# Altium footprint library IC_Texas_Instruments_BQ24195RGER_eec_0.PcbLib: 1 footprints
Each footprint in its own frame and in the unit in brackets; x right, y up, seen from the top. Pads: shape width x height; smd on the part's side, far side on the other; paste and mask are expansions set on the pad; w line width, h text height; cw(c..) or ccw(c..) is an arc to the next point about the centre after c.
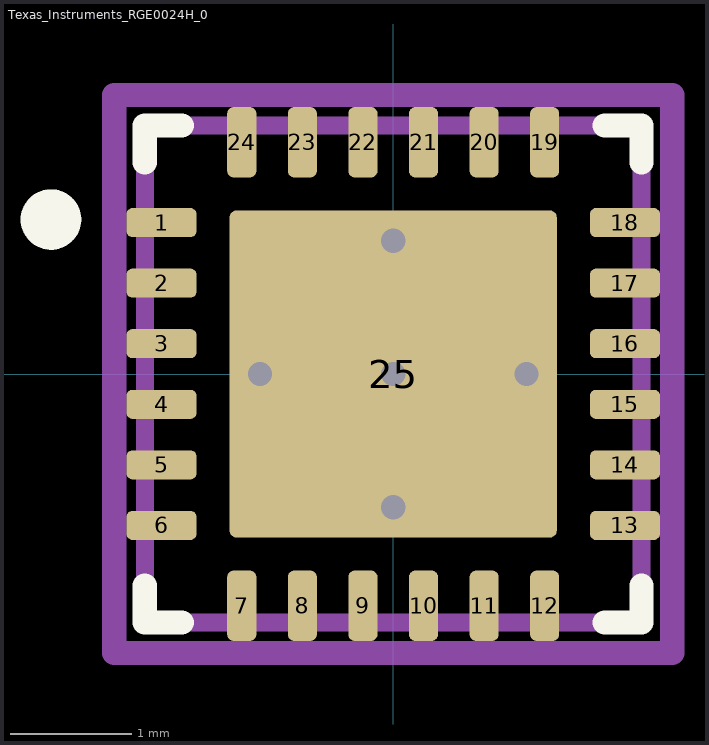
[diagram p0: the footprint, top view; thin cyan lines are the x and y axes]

## Texas_Instruments_RGE0024H_0 [mm]
pads (25):
  rrect42% 0.58x0.24 smd paste+0 mask+0: 1(-1.913,1.25) 2(-1.913,0.75) 3(-1.913,0.25) 4(-1.913,-0.25) 5(-1.913,-0.75) 6(-1.913,-1.25) 13(1.913,-1.25) 14(1.913,-0.75) 15(1.913,-0.25) 16(1.913,0.25) 17(1.913,0.75) 18(1.913,1.25)
  rrect42% 0.24x0.58 smd paste+0 mask+0: 7(-1.25,-1.913) 8(-0.75,-1.913) 9(-0.25,-1.913) 10(0.25,-1.913) 11(0.75,-1.913) 12(1.25,-1.913) 19(1.25,1.913) 20(0.75,1.913) 21(0.25,1.913) 22(-0.25,1.913) 23(-0.75,1.913) 24(-1.25,1.913)
  rrect4% 2.7x2.7 smd paste-1000 mask+0: 25(0,0)
via -1.1,0 diameter 0.5 hole 0.2
via 0,0 diameter 0.5 hole 0.2
via 1.1,0 diameter 0.5 hole 0.2
via 0,1.1 diameter 0.5 hole 0.2
via 0,-1.1 diameter 0.5 hole 0.2
Top Overlay:
  circle w0.25: c-2.825,1.275 r0.125
  lines w0.2: -2.05,-1.745 -2.05,-2.05 -1.745,-2.05 ; -2.05,1.745 -2.05,2.05 -1.745,2.05 ; 1.745,-2.05 2.05,-2.05 2.05,-1.745 ; 1.745,2.05 2.05,2.05 2.05,1.745
Top Paste:
  region: -0.1,0.15 -0.1,0.14 -0.108,0.122 -0.122,0.108 -0.14,0.1 -0.15,0.1 -1.238,0.1 -1.248,0.1 -1.266,0.108 -1.28,0.122 -1.288,0.14 -1.288,0.15 -1.288,1.238 -1.288,1.248 -1.28,1.266 -1.266,1.28 -1.248,1.288 -1.238,1.288 -0.15,1.288 -0.14,1.288 -0.122,1.28 -0.108,1.266 -0.1,1.248 -0.1,1.238
  region: 0.1,0.15 0.1,1.238 0.1,1.248 0.108,1.266 0.122,1.28 0.14,1.288 0.15,1.288 1.238,1.288 1.248,1.288 1.266,1.28 1.28,1.266 1.288,1.248 1.288,1.238 1.288,0.15 1.288,0.14 1.28,0.122 1.266,0.108 1.248,0.1 1.238,0.1 0.15,0.1 0.14,0.1 0.122,0.108 0.108,0.122 0.1,0.14
  region: -0.1,-0.15 -0.1,-1.238 -0.1,-1.248 -0.108,-1.266 -0.122,-1.28 -0.14,-1.288 -0.15,-1.288 -1.238,-1.288 -1.248,-1.288 -1.266,-1.28 -1.28,-1.266 -1.288,-1.248 -1.288,-1.238 -1.288,-0.15 -1.288,-0.14 -1.28,-0.122 -1.266,-0.108 -1.248,-0.1 -1.238,-0.1 -0.15,-0.1 -0.14,-0.1 -0.122,-0.108 -0.108,-0.122 -0.1,-0.14
  region: 0.15,-1.288 0.14,-1.288 0.122,-1.28 0.108,-1.266 0.1,-1.248 0.1,-1.238 0.1,-0.15 0.1,-0.14 0.108,-0.122 0.122,-0.108 0.14,-0.1 0.15,-0.1 1.238,-0.1 1.248,-0.1 1.266,-0.108 1.28,-0.122 1.288,-0.14 1.288,-0.15 1.288,-1.238 1.288,-1.248 1.28,-1.266 1.266,-1.28 1.248,-1.288 1.238,-1.288
Mechanical 10:
  lines w0.2: -2.302,-2.302 2.302,-2.302 2.302,2.302 -2.302,2.302 -2.302,-2.302
  text ".Designator" at 0,0 h1
Mechanical 12:
  lines w0.15: -2.05,-2.05 2.05,-2.05 2.05,2.05 -2.05,2.05 -2.05,-2.05
Mechanical 15:
  lines w0.1: -0.5,0 0.5,0 ; 0,-0.5 0,0.5
  lines w0.2: -2.302,-2.302 2.302,-2.302 2.302,2.302 -2.302,2.302 -2.302,-2.302
3D body "IC_Texas_Instruments_BQ24195RGER_eec.STEP": height 0.25, standoff 0, extent -2.302,-2.302 2.302,2.302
